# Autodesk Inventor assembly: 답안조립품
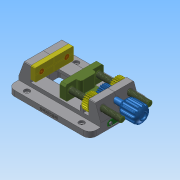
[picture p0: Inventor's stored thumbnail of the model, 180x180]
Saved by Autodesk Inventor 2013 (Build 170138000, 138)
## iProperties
Created: 2018-03
Part Number: 답안조립품
Document SubType Name: Assembly
Designer: Administrator
Mass: 1034.81 g
Surface Area: 918.51 cm^2
Volume: 340.422 cm^3
Density: 3.0398 g/cm^3
Author: Administrator
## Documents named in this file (10)
- C:\Users\Administrator\Desktop\380308V1014\답안조립품.iam
- C:\Users\Administrator\Desktop\380308V1014\바이스본체 A.ipt
- C:\Users\Administrator\Desktop\380308V1014\고정 플레이트.ipt
- C:\Users\Administrator\Desktop\380308V1014\바이스본체 B.ipt
- C:\Users\Administrator\Desktop\380308V1014\스퍼기어.ipt
- C:\Users\Administrator\Desktop\380308V1014\슬라이딩 부품.ipt
- C:\Users\Administrator\Desktop\380308V1014\십자오목머리나사 M3.ipt
- C:\Users\Administrator\Desktop\380308V1014\십자오목머리나사 M4.ipt
- C:\Users\Administrator\Desktop\380308V1014\지지대.ipt
- C:\Users\Administrator\Desktop\380308V1014\핸들.ipt
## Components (3 placed, 2 different names)
1. 고정 플레이트:1
2. 핸들:1 — 각도:1
3. 고정 플레이트:2
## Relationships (1: Angle 1)
- 각도:1 [Angle]: 핸들:1
